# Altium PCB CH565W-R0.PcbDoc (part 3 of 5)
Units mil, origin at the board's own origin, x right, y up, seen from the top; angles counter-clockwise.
Board outline 3947.04 x 3947.04 mil, 4 copper layers (Top Layer, Layer 1, Layer 2, Bottom Layer), stack 23.756 mil thick; 204 components, 168 nets, 932 pads, 1005 vias.
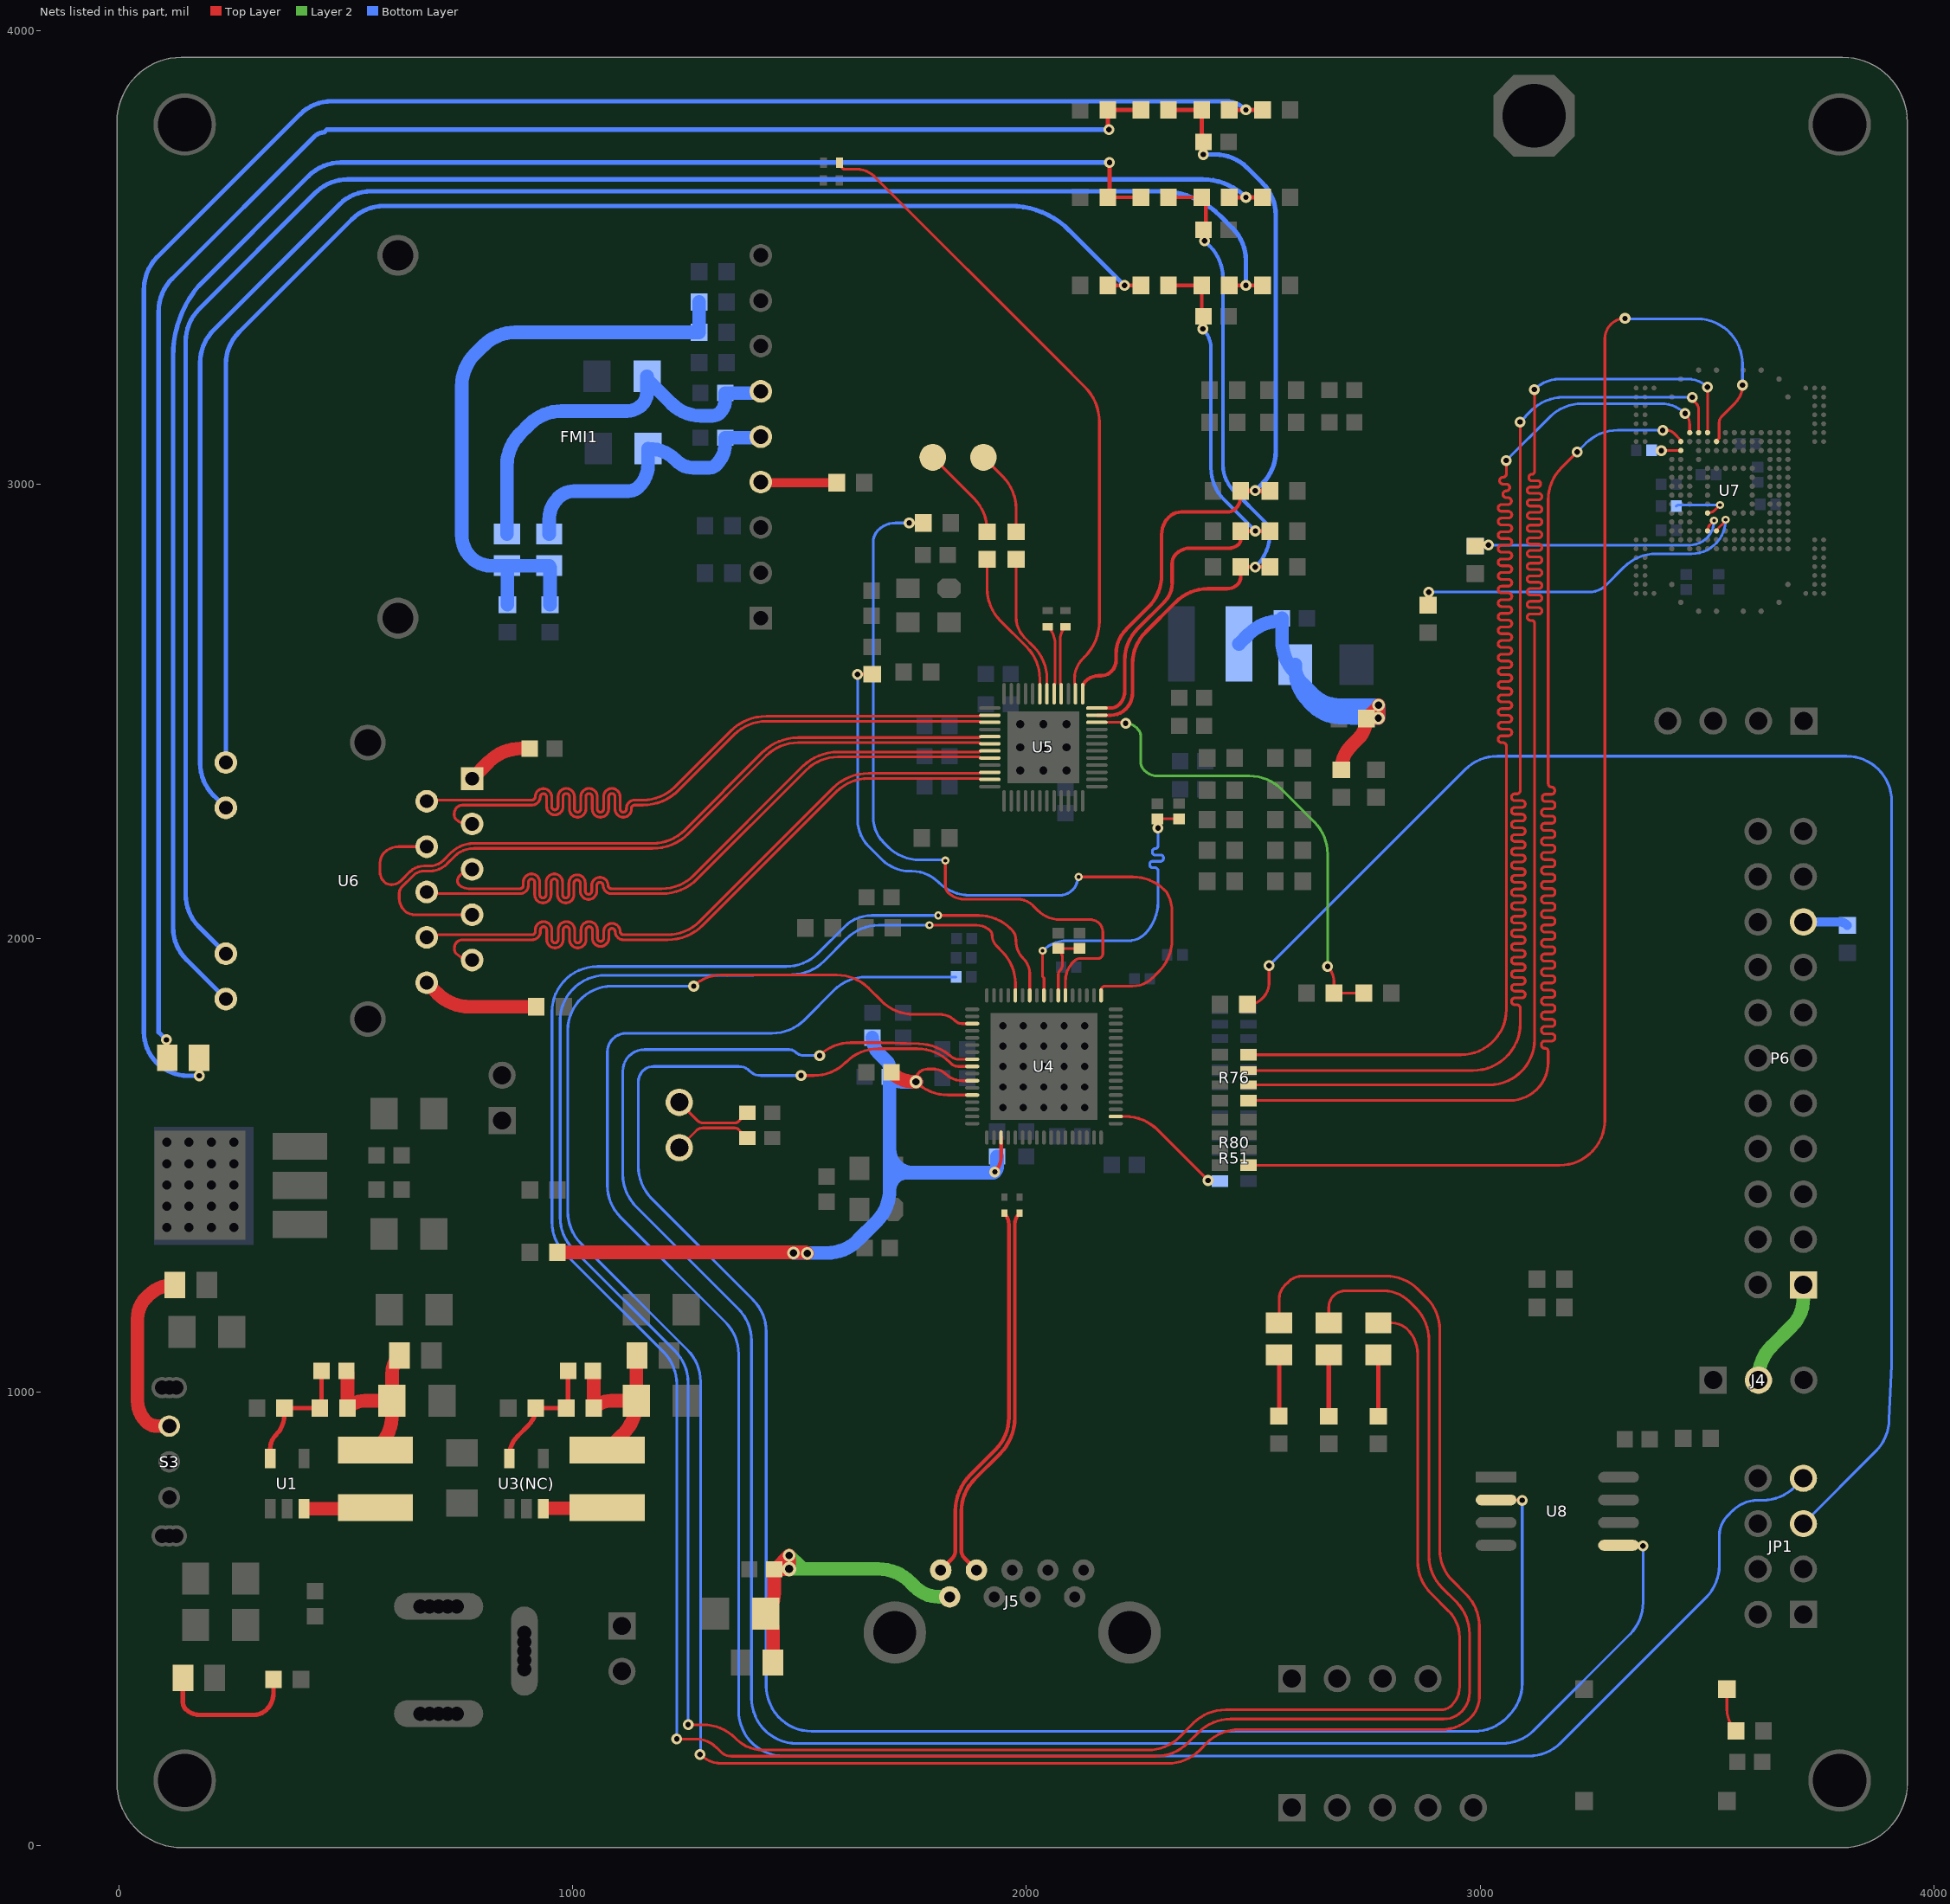
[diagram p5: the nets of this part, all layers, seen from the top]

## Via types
v1: diameter 17.72, hole 7.87, Top Layer to Bottom Layer, 556 vias
v2: diameter 24, hole 12, Top Layer to Bottom Layer, 366 vias
v3: diameter 28, hole 16, Top Layer to Bottom Layer, 63 vias
v4: diameter 17.72, hole 7.87, Top Layer to Bottom Layer, tented both sides, 8 vias
v5: diameter 24, hole 12, Top Layer to Bottom Layer, tented both sides, 5 vias
v6: diameter 26, hole 14, Top Layer to Bottom Layer, 2 vias
v7: diameter 19.68, hole 10, Top Layer to Bottom Layer, 1 vias
v8: diameter 20, hole 10, Top Layer to Bottom Layer, 1 vias
v9: diameter 28, hole 16, Top Layer to Bottom Layer, tented both sides, 1 vias
v10: diameter 32, hole 18, Top Layer to Bottom Layer, 1 vias
v11: diameter 17.72, hole 12, Top Layer to Bottom Layer, 1 vias

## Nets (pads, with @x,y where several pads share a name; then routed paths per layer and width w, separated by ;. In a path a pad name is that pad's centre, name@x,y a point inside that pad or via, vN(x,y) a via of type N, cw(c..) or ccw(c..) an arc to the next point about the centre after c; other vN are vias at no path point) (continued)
HSI_p: C30.1 U5.38 | length 1446.3
  Top Layer w6.07: C30.1@1587.84,3709.36 1590.71,3706.49 cw(c1585.97,3701.74) 1592.68,3701.74 1592.68,3701.48 ccw(c1598.75,3701.48) 1594.45,3697.19 ccw(c1598.75,3701.48) 1598.75,3695.41 1625.45,3695.41 cw(c1625.45,3639.8) 1664.77,3679.12 2071.93,3271.96 2128.33,3215.56 cw(c2049.98,3137.2) 2160.79,3137.2 2160.79,2698.77 cw(c2049.79,2698.77) 2128.28,2620.28 2124.36,2616.35 ccw(c2169.24,2571.47) 2105.76,2571.47 2105.76,2563.07 ccw(c2109.76,2563.07) 2106.93,2560.25 cw(c2104.11,2557.42) 2108.1,2557.42 U5.38@2108.1,2538.9
HSO_CK_n: R15.2 U5.43 | length 335.7
  Top Layer w6: R15.2@1913.28,2835.12 1913.28,2770.68 ccw(c2013.28,2770.68) 1942.57,2699.97 2000.07,2642.47 cw(c1929.36,2571.76) 2029.36,2571.76 U5.43@2029.36,2538.9
HSO_CK_p: R16.2 U5.42 | length 317.3
  Top Layer w6: R16.2@1977.14,2835.12 1977.14,2708.23 ccw(c2042.31,2708.23) 1996.19,2662.19 ; 1996.23,2662.15 2015.82,2642.56 cw(c1945.11,2571.85) 2045.11,2571.85 U5.42@2045.11,2538.9
HSO_n: C29.1 U5.41 | length 152.7
  Top Layer w6.07: C29.1@2047.23,2686.71 cw(c2008.67,2648.15) 2063.2,2648.15 2063.2,2563.07 cw(c2059.2,2563.07) 2062.03,2560.25 ccw(c2064.85,2557.42) 2060.86,2557.42 U5.41@2060.86,2538.9
HSO_p: C28.1 U5.40 | length 151.6
  Top Layer w6.07: U5.40@2076.61,2538.9 2076.61,2557.42 ccw(c2072.61,2557.42) 2075.44,2560.25 cw(c2078.26,2563.07) 2074.27,2563.07 2074.27,2657.81 cw(c2115.13,2657.81) C28.1@2086.23,2686.71
INTB: R35.1 R36.1 U5.34 | length 1060.9
  Top Layer w6: U5.34@2155.35,2475.91 2186.16,2475.91 ; 2187.54,2476.07 cw(c2186.16,2481.91) 2186.16,2475.91 ; v2(2218.68,2473.8) ccw(c2213.58,2468.7) 2213.58,2475.91 2186.16,2475.91 ; v2(2663.89,1937.58) cw(c2630.17,1903.86) 2677.86,1903.86 R36.1@2677.86,1879.13 R35.1@2743.57,1879.13
  Layer 2 w6: v2(2218.68,2473.8) cw(c2218.68,2440.07) 2242.53,2463.92 2245.76,2460.69 cw(c2231.12,2446.05) 2251.83,2446.05 2251.83,2389.59 ccw(c2279.93,2389.59) 2260.06,2369.72 ccw(c2289.34,2399) 2289.34,2357.59 2491.62,2357.59 cw(c2491.62,2257.59) 2562.33,2328.3 2634.6,2256.03 cw(c2563.89,2185.32) 2663.89,2185.32 v2(2663.89,1937.58)
LED0: D3.2 U4.54 | length 5823.5
  Top Layer w6: v2(1280.4,200.58) ccw(c1328.73,248.91) 1328.73,180.57 2311.21,180.57 ccw(c2311.21,280.57) 2381.92,209.85 2397.98,225.91 cw(c2468.69,155.2) 2468.69,255.2 2915.13,255.2 ccw(c2915.13,346.3) 2979.55,281.88 ccw(c2934.16,327.27) 2998.35,327.27 2998.35,482.96 ccw(c2898.35,482.96) 2969.06,553.67 2939.05,583.68 cw(c3006.69,651.31) 2911.04,651.31 2911.04,1136.81 ccw(c2811.76,1136.81) 2881.96,1207.01 2863.15,1225.82 ccw(c2792.43,1155.11) 2792.43,1255.11 2608.29,1255.11
  Top Layer w6.07: v2(1266.41,1894.11) cw(c1325.85,1834.66) 1325.85,1918.73 1347.45,1918.73 ; 1340.02,1918.46 cw(c1347.45,1818.73) 1347.45,1918.73 ; U4.54@1880.41,1811.61 1856.9,1811.61 cw(c1856.9,1829.57) 1844.2,1816.87 ccw(c1807.52,1780.18) 1807.52,1832.07 1751.28,1832.07 cw(c1751.28,1932.07) 1680.57,1861.35 1652.48,1889.44 ccw(c1581.77,1818.73) 1581.77,1918.73 1347.45,1918.73 ; D3.2@2557.01,1151.68 2557.01,1204.73 cw(c2598.61,1204.73) 2569.2,1234.14 2577.36,1242.3 cw(c2608.29,1211.37) 2608.29,1255.11
  Bottom Layer w6.07: v2(1266.41,1894.11) 1085.7,1894.11 ccw(c1085.7,1797.2) 988.79,1797.2 988.79,1397.57 ccw(c1088.79,1397.57) 1018.08,1326.86 1252.11,1092.83 cw(c1181.4,1022.12) 1281.4,1022.12 v2@1281.4,200.58
LED0/PHYAD0: C53.1 R28.2 R29.1 R58.2 R59.2 U5.35 | length 1544.5
  Top Layer w8: U5.35@2155.35,2491.66 2186.15,2491.66 ccw(c2186.15,2537.98) 2218.9,2505.23 ccw(c2183.24,2540.89) 2233.68,2540.89 2233.68,2604.28 cw(c2333.68,2604.28) 2262.97,2674.99 2328.95,2740.98 cw(c2399.66,2670.27) 2399.66,2770.27 2441.86,2770.27 ccw(c2441.86,2803.97) 2465.69,2780.14 ccw(c2450.2,2795.63) 2472.1,2795.63 R28.2@2472.1,2818.39 v2(2504.35,2818.39) R29.1@2536.59,2818.39 ; R58.2@2313.17,3633.33 R59.2@2386.48,3633.33 cw(c2364.97,3611.82) 2395.39,3611.82 C53.1@2395.39,3562.09 ; C53.1@2390.39,3562.09 2390.39,3542.61 ccw(c2398,3542.61) v2(2392.62,3537.23)
  Bottom Layer w8: v2(2392.62,3537.23) 2403.86,3525.99 cw(c2333.15,3455.28) 2433.15,3455.28 2433.15,3043.33 ccw(c2512.97,3043.33) 2456.53,2986.89 2526.81,2916.6 cw(c2503.17,2892.97) 2536.6,2892.97 2536.6,2892.07 cw(c2436.6,2892.07) 2507.31,2821.36 v2(2504.35,2818.39)
LED1: D4.2 U4.45 | length 5942.9
  Top Layer w6: v2(1229.1,234.45) 1270.53,234.45 cw(c1270.53,168.24) 1317.35,215.06 1326.5,205.9 ccw(c1349.22,228.62) 1349.22,196.49 ; v1(1805.62,2050.05) 1894.54,2050.05 cw(c1894.54,1950.05) 1965.25,2020.76 1966.93,2019.08 cw(c1943.64,1995.78) 1976.58,1995.78 ccw(c2035.26,1995.78) 1986.42,1963.26 ccw(c2035.26,1995.78) 1993.77,1954.29 cw(c1961.59,1922.11) 2007.1,1922.11 U4.45@2007.1,1873.9 ; D4.2@2666.38,1151.68 2666.38,1185.84 cw(c2702.74,1185.84) 2677.03,1211.54 cw(c2703.47,1185.11) 2703.47,1222.49 2722.55,1222.49
  Top Layer w6.07: 1349.22,196.49 2285.24,196.49 ccw(c2285.24,296.49) 2355.95,225.78 2379.26,249.09 cw(c2449.97,178.38) 2449.97,278.38 2919.97,278.38 ccw(c2919.97,333.47) 2958.92,294.52 ccw(c2915.95,337.49) 2976.73,337.49 2976.73,466.1 ccw(c2876.73,466.1) 2947.44,536.81 2916.43,567.82 cw(c2987.14,638.53) 2887.14,638.53 2887.14,1114.26 ccw(c2787.14,1114.26) 2857.85,1184.97 2843.63,1199.19 ccw(c2787.36,1142.92) 2787.36,1222.49 2722.55,1222.49
  Bottom Layer w6: v2(1229.1,234.45) 1229.1,1016.88 ccw(c1129.1,1016.88) 1199.81,1087.59 983.16,1304.24 cw(c1053.87,1374.95) 953.87,1374.95 953.87,1837.59 cw(c1053.87,1837.59) 1053.73,1937.59 cw(c1053.87,1837.59) 1053.87,1937.59 1470.08,1937.59 ccw(c1470.08,2037.59) 1540.79,1966.88 1599.42,2025.5 cw(c1658.68,1966.23) 1658.68,2050.05 v1(1805.62,2050.05)
LED1/CFG_LDO0: C58.1 R37.2 R38.1 R71.2 R72.2 U5.36 | length 1320.4
  Top Layer w8: U5.36@2155.35,2507.41 2185.36,2507.41 ccw(c2185.36,2534.62) 2204.61,2515.38 ccw(c2175.97,2544.02) 2216.47,2544.02 2216.47,2612.35 cw(c2316.47,2612.35) 2245.76,2683.06 2304.03,2741.33 ccw(c2262.41,2782.95) 2321.27,2782.95 2321.27,2826.36 cw(c2350.68,2826.36) 2329.88,2847.16 cw(c2360.56,2816.49) 2360.56,2859.87 2446.75,2859.87 ccw(c2446.75,2890.29) 2468.26,2868.78 ccw(c2458.98,2878.06) 2472.1,2878.06 R37.2@2472.1,2897.13 R38.1@2536.59,2897.13 ; R71.2@2313.17,3439.1 R72.2@2386.48,3439.1 2386.48,3380.36 ccw(c2399.84,3380.36) C58.1@2390.39,3370.91 ccw(c2394.06,3367.25) 2388.87,3367.25 v2(2388.87,3343.33)
  Bottom Layer w8: v2(2388.87,3343.33) cw(c2345.72,3300.18) 2406.75,3300.18 2406.75,3037.06 ccw(c2506.75,3037.06) 2436.04,2966.35 v2(2504.64,2897.75)
LED2: D5.2 U4.47 | length 5531.7
  Top Layer w6: v2(1254.15,266) 1287.31,266 cw(c1287.31,166) 1358.02,236.71 1360.58,234.15 ccw(c1418.62,292.2) 1418.62,210.11 2268.45,210.11 ccw(c2268.45,307.09) 2337.03,238.52 2368.08,269.57 cw(c2438.79,198.86) 2438.79,298.86 2914.27,298.86 ccw(c2914.27,331.39) 2937.27,308.38 ccw(c2895.1,350.55) 2954.74,350.55 2954.74,458.9 ccw(c2873.41,458.9) 2930.92,516.4 2891.67,555.65 cw(c2962.38,626.36) 2862.38,626.36 2862.38,1082.73 ccw(c2784.65,1082.73) 2839.61,1137.7 ccw(c2805.86,1103.95) 2805.86,1151.68 D5.2@2775.75,1151.68 ; v1(1786.1,2028.55) 1890.11,2028.55 cw(c1890.11,1985.28) 1920.71,2015.87 cw(c1912.39,2007.55) 1924.15,2007.55 ccw(c1959.87,2007.55) 1934.61,1982.3 1946.31,1970.6 cw(c1875.6,1899.89) 1975.6,1899.89 U4.47@1975.6,1873.9
  Bottom Layer w6: v2(1254.15,266) 1254.15,1019.48 ccw(c1154.15,1019.48) 1224.86,1090.19 1001.28,1313.77 cw(c1071.99,1384.48) 971.99,1384.48 971.99,1818.23 cw(c1071.99,1818.23) 972.05,1821.42 cw(c1071.99,1818.23) 1071.99,1918.23 1398.39,1918.23 1483.26,1920.24 cw(c1483.42,1914.24) 1483.42,1920.24 ccw(c1483.42,2020.24) 1554.13,1949.53 1604,1999.39 cw(c1674.38,1929) 1674.38,2028.55 v1(1786.1,2028.55)
LED2/CFG_LDO1: C54.1 R39.2 R40.1 R67.2 R68.2 U5.37 | length 1758.8
  Top Layer w8: U5.37@2123.85,2538.9 2123.85,2551.15 cw(c2145.58,2551.15) 2130.21,2566.51 2130.33,2566.63 cw(c2159.06,2537.9) 2159.06,2578.53 2164.09,2578.53 ccw(c2164.09,2611.36) 2187.31,2588.15 ccw(c2162.64,2612.81) 2197.53,2612.81 2197.53,2627.01 cw(c2273.45,2627.01) 2219.76,2680.7 2268.71,2729.65 ccw(c2198,2800.36) 2298,2800.36 2298,2889.84 cw(c2352.17,2889.84) 2313.87,2928.15 cw(c2341.34,2900.68) 2341.34,2939.53 2442.41,2939.53 ccw(c2442.41,2966.39) 2461.41,2947.39 ccw(c2435.58,2973.22) 2472.1,2973.22 R39.2@2472.1,2985.87
  Top Layer w10: R67.2@2313.17,3826.22 R68.2@2386.48,3826.22 2386.48,3776.61 ccw(c2416.91,3776.61) C54.1@2395.39,3755.1 ; v2(2389.9,3727.84) ccw(c2388.72,3729.02) 2390.39,3729.02 C54.1@2390.39,3755.1 ; R39.2@2472.1,2985.87 R40.1@2536.59,2985.87
  Bottom Layer w10: v2(2389.9,3727.84) 2415.82,3727.84 cw(c2415.82,3627.84) 2486.53,3698.55 2520.34,3664.74 cw(c2449.63,3594.03) 2549.63,3594.03 2549.63,3073.45 cw(c2449.63,3073.45) 2520.34,3002.74 v2(2504.19,2986.59) ccw(c2514.19,2986.59) v2@2504.19,2986.51
LED_blue_n: D2.2 R68.1 R69.1 | length 4549.1
  Top Layer w10: D2.2@175.98,1736.01 175.98,1697.89 ccw(c177.69,1697.89) v2(176.48,1696.68) ; R68.1@2447.11,3826.22 v2(2483.77,3826.22) R69.1@2520.42,3826.22
  Bottom Layer w10: v2(176.48,1696.68) 151.66,1696.68 cw(c151.66,1794.39) 82.57,1725.3 cw(c150.27,1793) 54.53,1793 54.53,3300.97 54.53,3430.89 cw(c154.53,3430.89) 55.44,3444.37 cw(c154.53,3430.89) 83.82,3501.61 398.2,3815.99 cw(c468.92,3745.28) 468.92,3845.28 2437.74,3845.28 cw(c2437.74,3780.19) v2(2483.77,3826.22)
LED_blue_p: D2.1 R66.2 R67.1 | length 4051.4
  Top Layer w10: v2(103.69,1775.98) cw(c103.69,1773.77) 105.9,1773.77 D2.1@105.9,1736.01 ; v2(2181.54,3782.57) cw(c2187.14,3788.17) 2179.23,3788.17 R66.2@2179.23,3826.22 R67.1@2252.54,3826.22
  Bottom Layer w10: v2(103.69,1775.98) 87,1792.65 87,3242.91 87,3382.79 cw(c187,3382.79) 87.44,3392.17 cw(c187,3382.79) 116.29,3453.5 430.48,3767.69 cw(c451.38,3746.8) 451.38,3776.35 457.6,3782.57 v2(2181.54,3782.57)
LED_green_n: R72.1 R73.1 U6.12 | length 3681.8
  Top Layer w8: R72.1@2447.11,3439.1 v2(2483.77,3439.1) R73.1@2520.42,3439.1
  Bottom Layer w10: U6.12@234.95,2287.54 207.86,2314.63 cw(c278.57,2385.34) 178.57,2385.34 178.57,3269.55 cw(c278.57,3269.55) 180.33,3288.23 cw(c278.57,3269.55) 207.86,3340.26 485.02,3617.42 cw(c555.73,3546.71) 555.73,3646.71 2295.99,3646.71 cw(c2295.99,3461.18) 2427.18,3592.37 2454.48,3565.07 cw(c2383.77,3494.36) 2483.77,3494.36 v2(2483.77,3439.1)
LED_green_p: R70.2 R71.1 U6.11 | length 3157
  Top Layer w8: R70.2@2179.23,3439.1 v2(2215.88,3439.1) R71.1@2252.54,3439.1
  Bottom Layer w10: U6.11@234.95,2387.54 234.95,3265.49 cw(c334.95,3265.49) 264.24,3336.2 513.1,3585.06 cw(c583.81,3514.35) 583.81,3614.35 1964.21,3614.35 cw(c1964.21,3429.85) 2094.67,3560.31 v2(2215.88,3439.1)
LED_yellow_n: R59.1 R61.1 U6.13 | length 3966.9
  Top Layer w10: R59.1@2447.11,3633.33 v2(2483.77,3633.33) R61.1@2520.42,3633.33
  Bottom Layer w10: U6.13@234.95,1965.89 175.89,2024.94 cw(c246.6,2095.65) 146.6,2095.65 146.6,3315.92 cw(c246.6,3315.92) 175.89,3386.63 432.82,3643.57 cw(c503.53,3572.85) 442.14,3651.79 cw(c503.53,3572.85) 457.66,3661.71 cw(c503.53,3572.85) 503.53,3672.85 2388.35,3672.85 cw(c2388.35,3537.92) v2(2483.77,3633.33)
LED_yellow_p: R57.2 R58.1 U6.14 | length 3897.1
  Top Layer w8: R57.2@2179.23,3633.33 R58.1@2252.54,3633.33
  Top Layer w10: R57.2@2179.23,3633.33 ccw(c2174.48,3638.08) 2181.2,3638.08 2183.11,3640 v2(2183.11,3709.99)
  Bottom Layer w10: U6.14@234.95,1865.88 147.83,1953.01 cw(c218.54,2023.72) 118.54,2023.72 118.54,3282.88 cw(c360.1,3282.84) 173.97,3436.81 417.86,3680.7 cw(c488.57,3609.99) 488.57,3709.99 v2(2183.11,3709.99)
MAC_125M: R62.2 U4.40 | length 1595
  Top Layer w6: v2(1741.47,2915.5) 1741.53,2915.44 R62.2@1772.45,2915.44 ; v1(1821.29,2171.08) 1821.29,2114.81 ccw(c1841.25,2114.81) 1827.13,2100.69 ccw(c1862.6,2136.16) 1862.6,2086 1979.94,2086 cw(c1979.94,2037.54) 2014.21,2071.81 2024.38,2061.64 ccw(c2074.66,2111.92) 2042.88,2048.31 ccw(c2074.66,2111.92) 2074.66,2040.82 2140.85,2040.82 cw(c2140.85,2013.19) 2168.47,2013.19 2168.47,1966.22 cw(c2157.43,1966.22) 2157.43,1955.18 2118.97,1955.18 ccw(c2118.97,1934.69) 2104.48,1949.18 ccw(c2149.48,1904.17) 2091.15,1929.62 ccw(c2149.48,1904.17) 2085.84,1904.17 U4.40@2085.84,1873.9
  Bottom Layer w6: v2(1741.47,2915.5) 1711.59,2915.5 ccw(c1711.59,2860.6) 1672.77,2899.42 ccw(c1698.64,2873.55) 1662.05,2873.55 1662.05,2267.4 ccw(c1742.76,2267.4) 1685.69,2210.32 1694.28,2201.73 ccw(c1764.99,2272.44) 1764.99,2172.44 v1@1821.29,2172.44
MAC_EMCO: R60.2 U4.35 | length 1479.9
  Top Layer w6: v2(1627.69,2581.47) cw(c1629.99,2579.17) 1629.99,2582.42 R60.2@1659.93,2582.42 ; v1(2115,2135) 2234.16,2135 2234.26,2135.1 cw(c2234.26,2035.1) 2304.97,2105.81 2309.07,2101.71 cw(c2234.2,2058.14) 2320.82,2058.14 2320.82,1996.81 cw(c2220.82,1996.81) 2291.53,1926.1 2277.83,1912.39 cw(c2234.11,1956.1) 2234.11,1894.28 2173.47,1894.28 ccw(c2173.47,1885.39) 2164.58,1885.39 U4.35@2164.58,1873.9
  Bottom Layer w6: v2(1627.69,2581.47) 1627.69,2261.65 ccw(c1711.68,2261.65) 1652.29,2202.27 1681.45,2173.11 ccw(c1742.73,2234.39) 1742.73,2147.72 1747.55,2147.72 cw(c1747.55,2065.38) 1805.77,2123.61 ccw(c1876.18,2194.01) 1876.18,2094.44 2072.89,2094.44 ccw(c2072.89,2135.4) 2101.85,2106.44 ccw(c2074.94,2133.35) 2113,2133.35 2114.65,2135 v1(2115,2135)
MCU_3V3: C34.1 C35.2 C37.2 C46.2 R85.2 U4.3 U4.62 U4.64 | length 2087.9
  Top Layer w6.07: U4.64@1880.41,1654.13 1826.85,1654.13 cw(c1826.85,1753.51) v3(1756.58,1683.24) 1756.58,1688.57 cw(c1777.53,1688.57) 1762.71,1703.38 cw(c1782.17,1683.92) 1782.17,1711.44 1796.82,1711.44 cw(c1796.82,1677.35) 1800.23,1711.27 cw(c1796.82,1677.35) 1820.92,1701.46 ccw(c1859.15,1739.69) 1859.15,1685.63 U4.62@1880.41,1685.63
  Top Layer w8: v5(1930.24,1484.81) ccw(c1896.78,1518.27) 1944.11,1518.27 U4.3@1944.11,1560.34
  Top Layer w30: R85.2@965.93,1307.5 v3@1482.53,1307.5 ; v3(1486.31,1305.93) ccw(c1482.53,1302.15) v3@1482.53,1307.5 ; v3(1517,1305.31) ccw(c1511.72,1300.04) 1511.72,1307.5 v3@1482.53,1307.5 ; C37.2@1702.17,1704.14 ccw(c1752.63,1754.6) 1752.63,1683.24 v3(1756.58,1683.24)
  Bottom Layer w30: v3(1486.31,1305.93) 1559.86,1305.93 ccw(c1559.86,1403.24) 1628.67,1334.43 1669.06,1374.83 ccw(c1598.35,1445.54) 1698.35,1445.54 ; C35.2@1660.22,1780.43 ccw(c1708.7,1780.43) 1674.42,1746.15 1691.76,1728.8 cw(c1675.87,1712.9) 1698.35,1712.9 C34.1@1698.35,1694.32 ; 1698.35,1545.55 1698.35,1534.22 ; v3(1756.58,1683.24) 1725.09,1683.24 cw(c1725.09,1721.06) C34.1@1698.35,1694.32 ; C46.2@1935.23,1518.66 1935.23,1496.85 cw(c1918.2,1496.85) v5(1930.24,1484.81) cw(c1925.78,1489.28) 1925.78,1482.96 1749.61,1482.96 ; 1698.35,1445.54 cw(c1735.77,1445.54) 1735.77,1482.96 ; 1698.35,1445.54 1698.35,1482.96 ; 1698.35,1482.96 1698.35,1534.22 ; 1698.35,1482.96 1735.77,1482.96 ; 1698.35,1534.22 ccw(c1749.61,1534.22) 1749.61,1482.96 ; 1698.35,1534.22 C34.1@1698.35,1694.32 ; 1735.77,1482.96 1749.61,1482.96
MDI0_n: U5.3 U6.3 | length 1621.3
  Top Layer w6.07: U6.3@777.86,2251.78 767.69,2251.78 cw(c767.69,2287.75) 742.26,2262.32 cw(c751.53,2271.58) 738.43,2271.58 738.43,2274.19 cw(c758.08,2274.19) 744.18,2288.08 744.46,2288.36 cw(c756.66,2276.17) 756.66,2293.41 881.43,2293.41 909.98,2293.41 ccw(c909.98,2311.52) 928.08,2311.52 cw(c935.12,2311.52) 942.15,2311.52 942.15,2290.06 ccw(c960.25,2290.06) 978.36,2290.06 978.36,2311.98 cw(c985.39,2311.98) 992.43,2311.98 992.43,2284.79 ccw(c1010.53,2284.79) 1028.63,2284.79 1028.63,2311.98 cw(c1035.66,2311.98) 1042.7,2311.98 1042.7,2284.79 ccw(c1060.8,2284.79) 1078.9,2284.79 1078.9,2311.98 cw(c1085.94,2311.98) 1092.97,2311.98 1092.97,2284.79 ccw(c1111.08,2284.79) 1129.18,2284.79 1129.18,2286.38 cw(c1136.21,2286.38) 1136.21,2293.41 1144.78,2293.41 1154.38,2293.41 ccw(c1154.38,2404.3) 1232.79,2325.89 1355.86,2448.96 cw(c1426.57,2378.25) 1426.57,2478.25 1894.96,2478.25 cw(c1894.96,2474.26) 1897.78,2477.08 ccw(c1900.61,2479.91) 1900.61,2475.91 U5.3@1919.13,2475.91
MDI0_p: U5.2 U6.2 | length 1620.2
  Top Layer w6.07: U6.2@677.86,2301.78 cw(c684.38,2295.26) 684.38,2304.48 881.43,2304.48 909.98,2304.48 ccw(c909.98,2311.52) 917.01,2311.52 cw(c935.12,2311.52) 953.22,2311.52 953.22,2290.06 ccw(c960.25,2290.06) 967.29,2290.06 967.29,2311.98 cw(c985.39,2311.98) 1003.49,2311.98 1003.49,2284.79 ccw(c1010.53,2284.79) 1017.56,2284.79 1017.56,2311.98 cw(c1035.66,2311.98) 1053.77,2311.98 1053.77,2284.79 ccw(c1060.8,2284.79) 1067.84,2284.79 1067.84,2311.98 cw(c1085.94,2311.98) 1104.04,2311.98 1104.04,2284.79 ccw(c1111.08,2284.79) 1118.11,2284.79 1118.11,2286.38 cw(c1136.21,2286.38) 1136.21,2304.48 1144.78,2304.48 1154.31,2304.48 ccw(c1154.31,2404.48) 1225.02,2333.77 1296.38,2405.14 1348.06,2456.82 cw(c1426.52,2378.36) 1426.52,2489.32 1894.96,2489.32 ccw(c1894.96,2493.31) 1897.78,2490.49 cw(c1900.61,2487.66) 1900.61,2491.66 U5.2@1919.13,2491.66
MDI1_n: U5.6 U6.7 | length 1621.4
  Top Layer w6.07: U6.7@777.86,2051.78 651.16,2051.78 cw(c651.16,2084.04) 628.34,2061.23 cw(c654.82,2087.71) 617.38,2087.71 617.38,2099.56 cw(c636.41,2099.56) 622.95,2113.02 648.16,2138.22 cw(c671.81,2114.56) 671.81,2148.02 684.6,2148.02 ccw(c684.6,2201.55) 722.45,2163.7 739.03,2180.27 cw(c781.56,2137.74) 781.56,2197.89 1175.92,2197.89 ccw(c1175.92,2308.85) 1254.39,2230.39 1425.71,2401.72 cw(c1496.42,2331.01) 1496.42,2431.01 1894.96,2431.01 cw(c1894.96,2427.01) 1897.78,2429.84 ccw(c1900.61,2432.66) 1900.61,2428.67 U5.6@1919.13,2428.67
MDI1_p: U5.5 U6.4 | length 1620.9
  Top Layer w6.07: U6.4@677.86,2201.78 616.15,2201.78 ccw(c616.15,2156.64) 584.23,2188.56 ccw(c606.41,2166.38) 575.04,2166.38 575.04,2145.12 ccw(c603.81,2145.12) 583.46,2124.77 ccw(c599.89,2141.2) 599.89,2117.97 ccw(c599.89,2147.8) 620.98,2126.7 640.33,2146.05 cw(c671.81,2114.56) 671.81,2159.09 684.52,2159.09 ccw(c684.52,2201.76) 714.69,2171.58 731.23,2188.13 cw(c781.52,2137.84) 781.52,2208.96 1175.88,2208.96 ccw(c1175.88,2308.96) 1246.59,2238.25 1417.92,2409.57 cw(c1496.38,2331.11) 1496.38,2442.07 1894.96,2442.07 ccw(c1894.96,2446.07) 1897.78,2443.24 cw(c1900.61,2440.42) 1900.61,2444.41 U5.5@1919.13,2444.41
MDI2_n: U5.8 U6.6 | length 1620.6
  Top Layer w6.07: U6.6@677.86,2101.78 ccw(c686.89,2110.81) 686.89,2098.04 875.16,2098.04 883.73,2098.04 ccw(c883.73,2116.15) 901.83,2116.15 901.83,2123.52 cw(c908.86,2123.52) 915.9,2123.52 915.9,2095.76 ccw(c934,2095.76) 952.1,2095.76 952.1,2123.52 cw(c959.14,2123.52) 966.17,2123.52 966.17,2095.76 ccw(c984.28,2095.76) 1002.38,2095.76 1002.38,2121.59 cw(c1009.41,2121.59) 1016.45,2121.59 1016.45,2103.58 ccw(c1034.55,2103.58) 1052.65,2103.58 1052.65,2116.15 cw(c1059.69,2116.15) 1066.72,2116.15 ccw(c1084.82,2116.15) 1084.82,2098.04 1179.3,2098.04 1196.21,2098.04 ccw(c1196.21,2207.58) 1273.66,2130.13 1513.76,2370.22 cw(c1584.47,2299.51) 1584.47,2399.51 1894.96,2399.51 cw(c1894.96,2395.52) 1897.78,2398.34 ccw(c1900.61,2401.16) 1900.61,2397.17 U5.8@1919.13,2397.17
MDI2_p: U5.7 U6.5 | length 1620.1
  Top Layer w6.07: 749.65,2136.89 ccw(c759.18,2127.38) 745.72,2127.38 745.72,2125.35 ccw(c755.81,2125.35) 748.67,2118.22 ccw(c770.65,2140.19) 770.65,2109.11 875.16,2109.11 883.73,2109.11 ccw(c883.73,2116.15) 890.76,2116.15 890.76,2123.52 cw(c908.86,2123.52) 926.97,2123.52 926.97,2095.76 ccw(c934,2095.76) 941.04,2095.76 941.04,2123.52 cw(c959.14,2123.52) 977.24,2123.52 977.24,2095.76 ccw(c984.28,2095.76) 991.31,2095.76 991.31,2121.59 cw(c1009.41,2121.59) 1027.51,2121.59 1027.51,2103.58 ccw(c1034.55,2103.58) 1041.58,2103.58 1041.58,2116.15 cw(c1059.69,2116.15) 1077.79,2116.15 ccw(c1084.82,2116.15) 1084.82,2109.11 1179.3,2109.11 1196.03,2109.11 ccw(c1196.03,2208) 1265.96,2138.08 1505.96,2378.08 cw(c1584.42,2299.62) 1584.42,2410.58 1894.96,2410.58 ccw(c1894.96,2414.57) 1897.78,2411.75 cw(c1900.61,2408.92) 1900.61,2412.92 U5.7@1919.13,2412.92 ; 749.66,2136.89 755.14,2142.37 cw(c777.86,2119.64) U6.5@777.86,2151.78 ccw(c777.86,2132.27) U6.5@764.06,2146.07
MDI3_n: U5.11 U6.9 | length 1694.7
  Top Layer w6.07: U6.9@777.86,1951.78 cw(c777.86,2001.84) 742.47,1966.44 cw(c750.52,1974.5) 739.13,1974.5 739.13,1979.19 cw(c756.46,1979.19) 744.21,1991.45 cw(c756.18,1979.47) 756.18,1996.41 860.94,1996.41 861.01,1996.47 ; 891,1996.47 861.01,1996.47 ; 1155.46,1996.47 1111.37,1996.47 ; U5.11@1919.13,2349.93 1900.61,2349.93 cw(c1900.61,2353.92) 1897.78,2351.1 ccw(c1894.96,2348.27) 1894.96,2352.27 1651.77,2352.27 ccw(c1651.77,2252.27) 1581.05,2322.98 1286.96,2028.88 cw(c1208.72,2107.12) 1208.72,1996.47 1176.69,1996.47 1111.37,1996.47 ; 861.01,1996.47 901.71,1996.47 910.28,1996.47 ccw(c910.28,2014.58) 928.38,2014.58 928.38,2018.44 cw(c935.42,2018.44) 942.45,2018.44 942.45,1996.64 ccw(c960.55,1996.64) 978.66,1996.64 978.66,2018.44 cw(c985.69,2018.44) 992.72,2018.44 992.72,1996.64 ccw(c1010.83,1996.64) 1028.93,1996.64 1028.93,2018.44 cw(c1035.96,2018.44) 1043,2018.44 1043,2000.01 ccw(c1061.1,2000.01) 1079.2,2000.01 1079.2,2014.58 cw(c1086.24,2014.58) 1093.27,2014.58 ccw(c1111.37,2014.58) 1111.37,1996.47
MDI3_p: U5.10 U6.8 | length 1664.7
  Top Layer w6.07: U6.8@677.86,2001.78 cw(c691.92,1987.72) 691.92,2007.61 859.75,2007.61 859.81,2007.54 891,2007.54 901.71,2007.54 910.28,2007.54 ccw(c910.28,2014.58) 917.31,2014.58 917.31,2018.44 cw(c935.42,2018.44) 953.52,2018.44 953.52,1996.64 ccw(c960.55,1996.64) 967.59,1996.64 967.59,2018.44 cw(c985.69,2018.44) 1003.79,2018.44 1003.79,1996.64 ccw(c1010.83,1996.64) 1017.86,1996.64 1017.86,2018.44 cw(c1035.96,2018.44) 1054.07,2018.44 1054.07,2000.01 ccw(c1061.1,2000.01) 1068.14,2000.01 1068.14,2014.58 cw(c1086.24,2014.58) 1104.34,2014.58 ccw(c1111.37,2014.58) 1111.37,2007.54 ; 1155.46,2007.54 1111.37,2007.54 ; U5.10@1919.13,2365.67 1900.61,2365.67 ccw(c1900.61,2361.68) 1897.78,2364.5 cw(c1894.96,2367.33) 1894.96,2363.33 1761.62,2363.33 1651.62,2363.33 ccw(c1651.62,2252.63) 1573.33,2330.91 1279.26,2036.83 cw(c1208.54,2107.54) 1208.54,2007.54 1176.69,2007.54 1111.37,2007.54
MISO: JP1.5 R34.2 | length 3405
  Top Layer w6: R34.2@2487.06,1847.87 R34.2@2493.5,1854.3 ; R34.2@2487.06,1853.87 ccw(c2487.06,1901.6) R34.2@2493.5,1854.3 ; v2(2534.8,1939.56) 2534.8,1901.6 cw(c2487.06,1901.6) 2534.49,1896.19 cw(c2487.06,1901.6) R34.2@2493.5,1854.3
  Bottom Layer w6: v2(2534.8,1939.56) 2967.16,2371.92 cw(c3037.87,2301.21) 3037.87,2401.21 3808.13,2401.21 cw(c3808.13,2302.32) 3878.06,2372.25 cw(c3807.35,2301.53) 3907.35,2301.53 3907.35,1063.69 cw(c3796.35,1063.69) 3907.22,1058.42 3901.73,939.99 ccw(c3907.73,939.71) 3901.73,939.71 cw(c3801.73,939.71) 3872.44,869 JP1.5@3712.66,709.23
MISO1: U4.60 U8.2 | length 4472.2
  Top Layer w6.07: v2(1502.96,1697.04) 1531.07,1697.04 ccw(c1531.07,1797.04) 1601.78,1726.33 1602.64,1727.19 cw(c1672.6,1657.23) 1672.6,1756.17 1759.79,1756.17 cw(c1759.79,1656.17) 1830.5,1726.88 1833.54,1723.85 ccw(c1849.77,1740.08) 1849.77,1717.12 U4.60@1880.41,1717.12 ; U8.2@3035.36,761.58 3090.59,761.58 cw(c3090.59,758.38) v2(3092.85,760.64)
  Bottom Layer w6.07: v2(1502.96,1697.04) 1414.32,1697.04 cw(c1414.32,1731.19) 1390.18,1707.04 ccw(c1365.43,1682.29) 1365.43,1717.3 1178.02,1717.3 ccw(c1178.02,1683.67) 1144.39,1683.67 1144.39,1496.98 ccw(c1244.39,1496.98) 1173.68,1426.27 1397.05,1202.91 cw(c1326.34,1132.19) 1426.34,1132.19 1426.34,424.01 1426.34,351.49 ccw(c1526.34,351.49) 1526.34,251.49 2987.41,251.49 ccw(c2987.41,351.49) 3058.12,280.78 3063.56,286.22 ccw(c2992.85,356.93) 3092.85,356.93 v2(3092.85,760.64)
MOSI: JP1.7 R20.2 | length 5115
  Bottom Layer w6: R20.2@1844.8,1914.38 1646.21,1914.38 ccw(c1646.21,1814.38) 1575.5,1885.09 1510.02,1819.61 cw(c1439.31,1890.32) 1439.31,1790.32 1117.38,1790.32 ccw(c1117.38,1749.06) 1076.11,1749.06 1076.11,1455.17 ccw(c1176.11,1455.17) 1105.4,1384.45 1336.04,1153.81 cw(c1265.33,1083.1) 1365.33,1083.1 1365.33,296.91 ccw(c1465.33,296.91) 1465.33,196.91 1531.43,196.91 3107.02,196.91 ccw(c3107.02,296.91) 3177.73,226.2 3498.08,546.55 ccw(c3427.37,617.26) 3527.37,617.26 3527.37,681.95 cw(c3591.26,681.95) 3546.08,727.12 3556.74,737.78 ; 3556.77,737.81 cw(c3612.26,682.26) 3587.5,756.77 cw(c3612.26,682.26) 3612.26,760.77 3622.79,760.77 ccw(c3622.79,860.77) 3693.5,790.06 JP1.7@3712.66,809.23
MOSI1: U4.59 U8.5 | length 4654.2
  Top Layer w6.07: v2(1543.99,1741.25) cw(c1612.26,1672.98) 1612.26,1769.54 1680.69,1769.54 1762.89,1767.2 cw(c1759.79,1656.17) 1827.45,1744.26 1831.26,1741.33 cw(c1827.58,1736.51) 1831.84,1740.83 1831.87,1740.8 ccw(c1851.06,1760.04) 1851.06,1732.87 U4.59@1880.41,1732.87 ; U8.5@3305.36,661.58 ccw(c3308.24,664.46) 3308.24,660.38 v2(3359.33,660.38)
  Bottom Layer w6.07: v2(1543.99,1741.25) 1508.99,1741.25 cw(c1508.99,1766.64) 1491.04,1748.69 ccw(c1477.42,1735.07) 1477.42,1754.33 1157.72,1754.33 ccw(c1157.72,1706.63) 1110.03,1706.63 1110.03,1479.31 ccw(c1210.03,1479.31) 1139.32,1408.6 1364.49,1183.42 cw(c1293.78,1112.71) 1393.78,1112.71 1393.78,324.57 ccw(c1493.78,324.57) 1493.78,224.57 2930.39,224.57 3048.2,224.57 ccw(c3048.2,324.57) 3118.91,253.86 3330.04,464.98 ccw(c3259.33,535.69) 3359.33,535.69 v2(3359.33,660.38)
NetC1_2: C1.2 C4.2 L1.2 R1.1 R89.1 | length 408.6
  Top Layer w30: C4.2@500.73,1045.86 cw(c495.11,1040.24) 503.06,1040.24 R1.1@503.06,964.09 cw(c541.59,925.56) 541.59,980.05 C1.2@601.33,980.05 ; L1.2@564.59,871.4 572.04,878.85 ccw(c501.33,949.57) 601.33,949.57 C1.2@601.33,980.05 ; R89.1@617.88,1079.72 ccw(c657.83,1039.77) 601.33,1039.77 C1.2@601.33,980.05
NetC4_1: C4.1 R1.2 R3.2 U1.5 | length 280.7
  Top Layer w10: U1.5@332.87,852.63 332.87,874.69 cw(c374.77,874.69) 345.14,904.32 ccw(c299.07,950.39) 364.23,950.39 R3.2@364.23,964.09 R1.2@442.43,964.09 ccw(c434.46,972.06) 445.73,972.06 C4.1@445.73,1045.86
NetC12_1: C12.1 R4.2 R5.2 U3(NC).5 | length 280.7
  Top Layer w10: 860,852.63 860,857.86 cw(c923.26,857.86) 878.53,902.59 903.05,927.12 ccw(c866.08,964.09) R5.2@918.37,964.09 R4.2@985.52,964.09 ccw(c976.01,973.61) 989.47,973.61 C12.1@989.47,1045.86
NetC12_2: C12.2 C13.2 L3.2 R4.1 R90.1 | length 411.5
  Top Layer w30: C12.2@1044.47,1045.86 cw(c1040.39,1041.79) 1046.15,1041.79 R4.1@1046.15,964.09 cw(c1084.69,925.56) 1084.69,980.05 C13.2@1139.85,980.05 ; L3.2@1075.44,871.49 L3.2@1075.53,871.4 1110.56,906.43 ccw(c1039.85,977.14) 1139.85,977.14 C13.2@1139.85,980.05 ; R90.1@1141.72,1079.72 ccw(c1146.24,1075.2) 1139.85,1075.2 C13.2@1139.85,980.05
NetC19_1: C19.1 C20.1 FMI1.6 L5.2 | length 900.9
  Bottom Layer w30: L5.2@854.63,2891.15 854.63,3041.59 cw(c954.63,3041.59) 881.55,3109.85 cw(c954.63,3041.59) 883.92,3112.31 904.4,3132.79 cw(c975.11,3062.08) 975.11,3162.08 1118.85,3162.08 ccw(c1118.85,3209.11) 1152.1,3175.85 ccw(c1124.5,3203.45) 1160.76,3189 ccw(c1124.5,3203.45) 1163.53,3203.45 C19.1@1163.53,3232.55 ; C19.1@1163.53,3238.71 C19.1@1163.53,3232.55 ; FMI1.6@1414.36,3205.51 cw(c1405.46,3214.41) 1405.46,3201.83 C20.1@1336.16,3201.83 1336.16,3186.9 cw(c1296.49,3186.9) 1324.54,3158.84 cw(c1307.11,3176.27) 1307.11,3151.62 1282.05,3151.62 cw(c1282.05,3242.38) 1217.88,3178.21 C19.1@1163.53,3232.55
NetC21_1: C21.1 C22.1 FMI1.5 L6.2 | length 666.3
  Bottom Layer w6.07: FMI1.5@1409.13,3103.34 ccw(c1409.13,3110.74) FMI1.5@1414.36,3105.51
  Bottom Layer w30: L6.2@947.63,2891.15 947.63,2922.4 cw(c1016.45,2922.4) 967.79,2971.06 cw(c1002.98,2935.87) 1002.98,2985.64 1122.09,2985.64 ccw(c1122.09,3018.82) 1145.55,2995.36 ccw(c1096.16,3044.74) 1166.01,3044.74 C21.1@1166.01,3079.34 cw(c1166.01,2993.24) 1226.89,3054.12 1228.56,3052.45 ccw(c1265.7,3089.6) 1265.7,3037.07 1300.38,3037.07 ccw(c1300.38,3059.19) 1316.02,3043.54 ccw(c1267.4,3092.16) 1336.16,3092.16 C22.1@1336.16,3103.34 FMI1.5@1409.13,3103.34
NetC26_2: C26.2 R25.1 U4.43 | length 709.1
  Top Layer w6: v1(2035.67,1972.27) 2035.42,1972.02 2035.42,1915.4 2038.59,1912.23 U4.43@2038.59,1873.9 ; v2@2289.99,2239.77 cw(c2293.57,2243.36) 2288.5,2243.36 R25.1@2288.5,2263.11 2336.38,2263.11 C26.2@2336.45,2263.18
  Bottom Layer w6: v1(2035.67,1972.27) cw(c2089.35,1918.59) 2089.35,1994.51 2225.62,1994.51 ccw(c2225.62,2044.12) 2260.7,2009.04 ccw(c2189.99,2079.75) 2289.99,2079.75 2289.99,2146.14 2289.99,2149.14 ccw(c2283.69,2149.14) 2283.69,2155.44 2277.96,2155.44 cw(c2277.96,2161.74) 2271.66,2161.74 2271.66,2163.14 cw(c2277.96,2163.14) 2277.96,2169.44 2295.67,2169.44 ccw(c2295.67,2175.74) 2301.97,2175.74 2301.97,2177.14 ccw(c2295.67,2177.14) 2295.67,2183.44 2283.69,2183.44 cw(c2283.69,2189.74) 2277.39,2189.74 2277.39,2191.14 cw(c2283.69,2191.14) 2283.69,2197.44 ccw(c2283.69,2203.74) 2289.99,2203.74 2289.99,2237.77 v2@2289.99,2239.77
  other v2: 2289.99,2242.77
NetC27_1: C27.1 R26.2 U4.41 | length 154.6
  Top Layer w6: U4.41@2070.09,1873.9 2070.09,1918.54 cw(c2086.14,1918.54) 2074.79,1929.9 ccw(c2063.81,1940.88) 2079.34,1940.88 2079.34,1955.55 ccw(c2048.61,1955.55) R26.2@2070.34,1977.28 2116.28,1977.28 C27.1@2116.58,1977.58
NetC40_1: C40.1 U6.1 | length 150
  Top Layer w30: U6.1@777.86,2351.78 814.93,2388.85 cw(c885.64,2318.14) 885.64,2418.14 C40.1@904.72,2418.14
NetC44_2: C44.2 C45.2 L7.2 R54.1 R56.1 | length 1229.4
  Top Layer w30: R56.1@2694.06,2371.24 cw(c2769.63,2371.24) 2716.19,2424.68 2731.04,2439.53 ccw(c2686.55,2484.02) R54.1@2749.47,2484.02 ; R54.1@2749.47,2484.02 cw(c2752.08,2481.41) 2752.08,2485.11 v3(2775.69,2485.11) ccw(c2774.01,2486.78) 2776.38,2486.78 v3(2776.38,2514.01) cw(c2768.95,2514.01) 2774.21,2508.76 R54.1@2749.47,2484.02
  Bottom Layer w30: L7.2@2468.6,2648.83 2490.06,2670.28 cw(c2560.77,2599.57) 2560.77,2699.57 C45.2@2563.17,2699.57 ; C45.2@2563.17,2705.28 C45.2@2563.17,2699.57 ; C44.2@2592.47,2603.15 C44.2@2592.47,2598.15 ; 2631.3,2538.55 ccw(c2690.55,2597.8) 2690.55,2514.01 v3(2776.38,2514.01) ; C45.2@2563.17,2699.57 2563.17,2656.71 ccw(c2663.17,2656.71) 2592.46,2586 C44.2@2592.68,2585.78 ; C44.2@2592.47,2598.15 ccw(c2642.59,2598.15) C44.2@2594.52,2583.93 ; C44.2@2592.47,2598.15 2592.47,2592.35 ccw(c2692.47,2592.35) C44.2@2592.68,2585.78 ; C44.2@2592.68,2585.78 ccw(c2692.47,2592.35) 2621.75,2521.64 2632.34,2511.06 ccw(c2690.94,2569.66) 2690.94,2486.78 2707.94,2486.78 ; C44.2@2592.68,2585.78 C44.2@2594.52,2583.93 ; C44.2@2594.52,2583.93 ccw(c2642.59,2598.15) 2607.15,2562.71 2655.46,2514.39 ccw(c2726.17,2585.11) 2663.88,2506.88 ccw(c2726.17,2585.11) 2691.93,2491.15 ; 2691.93,2491.15 ccw(c2726.17,2585.11) 2707.94,2486.78 ; 2691.93,2491.15 2721.19,2491.15 ccw(c2721.19,2569.2) v3(2776.38,2514.01) ; 2707.94,2486.78 ccw(c2726.17,2585.11) 2726.17,2485.11 v3(2775.69,2485.11) ccw(c2774.01,2486.78) v3@2776.38,2486.78 ; 2707.94,2486.78 v3@2776.38,2486.78 ; v3@2776.38,2486.78 v3(2776.38,2514.01)
NetC60_1: C60.1 U7.K2 | length 41
  Top Layer w6: v5@3401.6,3074.64 3401.86,3074.9 3442.15,3074.9 U7.K2@3442.41,3075.16
  other v5: 3399.6,3074.64
NetC66_1: C66.1 C70.1 F2.1 J5.1 | length 773.4
  Top Layer w30: F2.1@1441.23,402.99 1441.23,471.63 ccw(c1385.59,471.63) C70.1@1424.93,510.97 ccw(c1378.77,557.14) 1444.06,557.14 C66.1@1444.06,608.6 ; v10(1476.8,609.33) cw(c1475.02,611.11) v10@1475.02,608.6 ; C66.1@1444.06,608.6 ccw(c1444.06,613.51) 1447.53,610.04 v3(1476.57,639.08) 1476.57,612.34 cw(c1471.28,612.34) v10@1475.02,608.6 ; C66.1@1444.06,608.6 v10@1475.02,608.6
  Layer 2 w30: v3(1476.57,639.08) v3@1476.8,638.85 ; J5.1@1830.72,547.91 1806.98,547.91 cw(c1806.98,622.07) 1754.54,569.63 1744.13,580.05 ccw(c1673.42,509.33) 1673.42,609.33 1513.11,609.33 ; v3@1476.8,638.85 v10(1476.8,609.33) 1513.11,609.33 ; v3@1476.8,638.85 1501.52,614.13 ccw(c1513.11,625.72) 1513.11,609.33
NetC71_2: C71.2 J5.8 | length 841.8
  Top Layer w8.22: J5.8@1889.78,606.96 1863.29,633.45 cw(c1879.77,649.93) 1856.46,649.93 1856.46,736.91 cw(c1956.46,736.91) 1885.75,807.62 1941.21,863.07 ccw(c1861.15,943.13) 1974.37,943.13 1974.37,1369.15 cw(c2008.98,1369.15) C71.2@1984.51,1393.63
NetC72_2: C72.2 J5.9 | length 841.3
  Top Layer w8.22: J5.9@1811.04,606.96 1835.63,631.55 ccw(c1817.24,649.93) 1843.24,649.93 1843.24,736.91 cw(c1956.46,736.91) 1876.4,816.97 1931.86,872.42 ccw(c1861.15,943.13) 1961.15,943.13 1961.15,1369.15 ccw(c1926.53,1369.15) C72.2@1951.01,1393.63
NetC73_2: C73.2 J1.1 | length 177
  Top Layer w6.07: J1.1@1234.59,1638.12 1275.38,1597.34 ccw(c1286.59,1608.56) 1286.59,1592.69 1357.24,1592.69 ccw(c1357.24,1604.4) 1365.52,1596.12 C73.2@1384.59,1615.2
NetC74_2: C74.2 J1.2 | length 175.9
  Top Layer w6.07: J1.2@1234.59,1538.12 1272.09,1575.62 cw(c1286.59,1561.11) 1286.59,1581.63 1357.14,1581.63 cw(c1357.14,1569.66) 1365.59,1578.12 C74.2@1384.59,1559.12
NetD1_1: D1.1 R2.1 | length 326.4
  Top Layer w10: D1.1@140.35,369.48 140.35,314.57 ccw(c160.01,314.57) 146.1,300.67 ccw(c177.52,332.08) 177.52,287.65 296.76,287.65 ccw(c296.76,327.64) 325.04,299.37 ccw(c289.05,335.35) 335.44,314.41 ccw(c289.05,335.35) 338.7,324.17 ccw(c289.05,335.35) 339.95,335.35 R2.1@339.95,365.91
NetD3_1: D3.1 R81.1 | length 135.5
  Top Layer w10: R81.1@2556.38,946.26 ccw(c2554.85,947.79) 2557.01,947.79 D3.1@2557.01,1081.6
NetD4_1: D4.1 R82.1 | length 135.5
  Top Layer w10: R82.1@2666.38,946.08 D4.1@2666.38,1081.6
NetD5_1: D5.1 R83.1 | length 137.8
  Top Layer w10: D5.1@2775.75,1081.6 2775.75,964.34 ccw(c2801.94,964.34) R83.1@2783.42,945.83
NetF1_1: F1.1 S3.2 | length 406.5
  Top Layer w30: S3.2@110.18,924.32 83.82,924.32 cw(c83.82,959.41) 59.02,934.6 cw(c104.46,980.04) 40.19,980.04 40.19,1160.52 cw(c107.25,1160.52) 59.83,1207.94 63.92,1212.02 cw(c120.84,1155.1) F1.1@120.84,1235.6
NetFMI1_4: FMI1.4 R19.2 | length 167.8
  Top Layer w20: FMI1.4@1414.36,3005.51 ccw(c1417.4,3008.56) 1417.4,3004.25 R19.2@1581.84,3004.25
NetJ4_2: J4.2 P6.1 | length 243.2
  Layer 2 w30: J4.2@3613.66,1025.68 3613.66,1029.89 cw(c3713.66,1029.89) 3642.95,1100.6 3687.97,1145.62 ccw(c3628.35,1205.24) 3712.66,1205.24 P6.1@3712.66,1235.79
NetL1_1: L1.1 U1.3 | length 157.4
  Top Layer w30: U1.3@410.67,742.39 L1.1@563.13,742.39 ; L1.1@560.13,742.39 ccw(c560.13,748.7) L1.1@564.59,744.24
NetL3_1: L3.1 U3(NC).3 | length 140.2
  Top Layer w30: 939.72,743.31 L3.1@1078.61,743.31 ; L3.1@1074.61,743.31 L3.1@1075.53,744.24
NetL5_1: L5.1 L6.1 R8.2 R11.2 R12.2 R13.2 | length 1387.7
  Bottom Layer w30: R12.2@855.52,2735.3 855.52,2818.92 ccw(c852.48,2818.92) L5.1@854.63,2821.07 ; R13.2@949.8,2735.3 949.8,2815.84 ccw(c942.4,2815.84) L6.1@947.63,2821.07 L5.1@854.63,2821.07 ; R8.2@1278.35,3402.57 R11.2@1278.35,3335.66 873.42,3335.66 ccw(c873.42,3235.66) 802.71,3306.37 784.29,3287.94 ccw(c855,3217.23) 755,3217.23 755,2888.99 ccw(c825.19,2888.99) 775.56,2839.36 ccw(c819.7,2883.51) 819.7,2821.07 L5.1@854.63,2821.07
NetP6_17: P6.17 R88.2 | length 99
  Bottom Layer w20: P6.17@3712.66,2035.79 3791.59,2035.79 cw(c3791.59,2010.27) R88.2@3809.64,2028.31
NetR15_1: R15.1 tp1.1 | length 209.7
  Top Layer w6: tp1.1@1793.44,3060.12 1883.99,2969.58 cw(c1813.28,2898.87) 1913.28,2898.87 R15.1@1913.28,2895.75
NetR16_1: R16.1 tp2.1 | length 189.9
  Top Layer w6: tp2.1@1905.1,3060.12 1947.85,3017.37 cw(c1877.14,2946.66) 1977.14,2946.66 R16.1@1977.14,2895.75
NetR27_2: R27.2 S2.2 | length 97.6
  Top Layer w6: S2.2@3544.26,344.38 3544.26,300.4 ccw(c3612.59,300.4) R27.2@3564.27,252.09
NetR51_1: R51.1 U4.19 | length 485.4
  Top Layer w6: U4.19@2196.78,1606.89 2217.62,1606.89 ; v2@2395.27,1471.5 2289.17,1577.6 ccw(c2218.46,1506.89) 2218.46,1606.89 2217.62,1606.89 ; v2@2399.07,1466.86 2288.33,1577.6 ccw(c2217.62,1506.89) 2217.62,1606.89
  other v2: 2400.13,1465.86
NetR55_1: R55.1 U6.10 | length 259.1
  Top Layer w30: U6.10@677.86,1901.78 701.6,1878.05 ccw(c772.31,1948.76) 772.31,1848.76 R55.1@919.3,1848.76
NetR74_2: R74.2 U7.U5 | length 130.8
  Top Layer w6: U7.U5@3501.47,2937.37 ccw(c3501.47,2960.56) 3517.87,2944.16 v4(3528.76,2955.05)
  Bottom Layer w6: R74.2@3432.34,2952.28 cw(c3439.03,2945.59) 3439.03,2955.05 v4(3528.76,2955.05)
NetR75_2: R75.2 R77.1 U7.W5 | length 552.1
  Top Layer w6: U7.W5@3501.47,2898 cw(c3521.54,2898) 3507.34,2912.19 v4(3515.78,2920.63)
  Bottom Layer w6: v2@3022.2,2866.57 3461.72,2866.57 ccw(c3461.72,2920.63) v4(3515.78,2920.63)
  other v2: 3018.2,2866.57
NetR76_5: R76.5 U7.J2 | length 3175.9
  Top Layer w6: R76.5@2489.51,1642.03 3065.22,1642.03 ccw(c3065.22,1727.02) 3150.21,1727.02 3150.21,1747.09 3150.21,1750.09 ccw(c3143.01,1750.09) 3143.01,1757.29 3142.41,1757.29 cw(c3142.41,1764.49) 3135.21,1764.49 3135.21,1766.09 cw(c3142.41,1766.09) 3142.41,1773.29 3158.01,1773.29 ccw(c3158.01,1780.49) 3165.21,1780.49 3165.21,1782.09 ccw(c3158.01,1782.09) 3158.01,1789.29 3142.41,1789.29 cw(c3142.41,1796.49) 3135.21,1796.49 3135.21,1798.09 cw(c3142.41,1798.09) 3142.41,1805.29 3158.01,1805.29 ccw(c3158.01,1812.49) 3165.21,1812.49 3165.21,1814.09 ccw(c3158.01,1814.09) 3158.01,1821.29 3142.41,1821.29 cw(c3142.41,1828.49) 3135.21,1828.49 3135.21,1830.09 cw(c3142.41,1830.09) 3142.41,1837.29 3158.01,1837.29 ccw(c3158.01,1844.49) 3165.21,1844.49 3165.21,1846.09 ccw(c3158.01,1846.09) 3158.01,1853.29 3142.41,1853.29 cw(c3142.41,1860.49) 3135.21,1860.49 3135.21,1862.09 cw(c3142.41,1862.09) 3142.41,1869.29 3158.01,1869.29 ccw(c3158.01,1876.49) 3165.21,1876.49 3165.21,1878.09 ccw(c3158.01,1878.09) 3158.01,1885.29 3142.41,1885.29 cw(c3142.41,1892.49) 3135.21,1892.49 3135.21,1894.09 cw(c3142.41,1894.09) 3142.41,1901.29 3158.01,1901.29 ccw(c3158.01,1908.49) 3165.21,1908.49 3165.21,1910.09 ccw(c3158.01,1910.09) 3158.01,1917.29 3142.41,1917.29 cw(c3142.41,1924.49) 3135.21,1924.49 3135.21,1926.09 cw(c3142.41,1926.09) 3142.41,1933.29 3158.01,1933.29 ccw(c3158.01,1940.49) 3165.21,1940.49 3165.21,1942.09 ccw(c3158.01,1942.09) 3158.01,1949.29 3142.41,1949.29 cw(c3142.41,1956.49) 3135.21,1956.49 3135.21,1958.09 cw(c3142.41,1958.09) 3142.41,1965.29 3158.01,1965.29 ccw(c3158.01,1972.49) 3165.21,1972.49 3165.21,1974.09 ccw(c3158.01,1974.09) 3158.01,1981.29 3142.41,1981.29 cw(c3142.41,1988.49) 3135.21,1988.49 3135.21,1990.09 cw(c3142.41,1990.09) 3142.41,1997.29 3158.01,1997.29 ccw(c3158.01,2004.49) 3165.21,2004.49 3165.21,2006.09 ccw(c3158.01,2006.09) 3158.01,2013.29 3142.41,2013.29 cw(c3142.41,2020.49) 3135.21,2020.49 3135.21,2022.09 cw(c3142.41,2022.09) 3142.41,2029.29 3158.01,2029.29 ccw(c3158.01,2036.49) 3165.21,2036.49 3165.21,2038.09 ccw(c3158.01,2038.09) 3158.01,2045.29 3142.41,2045.29 cw(c3142.41,2052.49) 3135.21,2052.49 3135.21,2054.09 cw(c3142.41,2054.09) 3142.41,2061.29 3158.01,2061.29 ccw(c3158.01,2068.49) 3165.21,2068.49 3165.21,2070.09 ccw(c3158.01,2070.09) 3158.01,2077.29 3142.41,2077.29 cw(c3142.41,2084.49) 3135.21,2084.49 3135.21,2086.09 cw(c3142.41,2086.09) 3142.41,2093.29 3158.01,2093.29 ccw(c3158.01,2100.49) 3165.21,2100.49 3165.21,2102.09 ccw(c3158.01,2102.09) 3158.01,2109.29 3142.41,2109.29 cw(c3142.41,2116.49) 3135.21,2116.49 3135.21,2118.09 cw(c3142.41,2118.09) 3142.41,2125.29 3158.01,2125.29 ccw(c3158.01,2132.49) 3165.21,2132.49 3165.21,2134.09 ccw(c3158.01,2134.09) 3158.01,2141.29 3142.41,2141.29 cw(c3142.41,2148.49) 3135.21,2148.49 3135.21,2150.09 cw(c3142.41,2150.09) 3142.41,2157.29 3158.01,2157.29 ccw(c3158.01,2164.49) 3165.21,2164.49 3165.21,2166.09 ccw(c3158.01,2166.09) 3158.01,2173.29 3142.41,2173.29 cw(c3142.41,2180.49) 3135.21,2180.49 3135.21,2182.09 cw(c3142.41,2182.09) 3142.41,2189.29 3158.01,2189.29 ccw(c3158.01,2196.49) 3165.21,2196.49 3165.21,2198.09 ccw(c3158.01,2198.09) 3158.01,2205.29 3142.41,2205.29 cw(c3142.41,2212.49) 3135.21,2212.49 3135.21,2214.09 cw(c3142.41,2214.09) 3142.41,2221.29 3158.01,2221.29 ccw(c3158.01,2228.49) 3165.21,2228.49 3165.21,2230.09 ccw(c3158.01,2230.09) 3158.01,2237.29 3142.41,2237.29 cw(c3142.41,2244.49) 3135.21,2244.49 3135.21,2246.09 cw(c3142.41,2246.09) 3142.41,2253.29 3158.01,2253.29 ccw(c3158.01,2260.49) 3165.21,2260.49 3165.21,2262.09 ccw(c3158.01,2262.09) 3158.01,2269.29 3142.41,2269.29 cw(c3142.41,2276.49) 3135.21,2276.49 3135.21,2278.09 cw(c3142.41,2278.09) 3142.41,2285.29 3158.01,2285.29 ccw(c3158.01,2292.49) 3165.21,2292.49 3165.21,2294.09 ccw(c3158.01,2294.09) 3158.01,2301.29 3144.2,2301.29 cw(c3144.2,2308.49) 3137,2308.49 3137,2310.09 cw(c3144.2,2310.09) 3144.2,2317.29 3157.41,2317.29 ccw(c3157.41,2324.49) 3164.61,2324.49 3164.61,2326.09 ccw(c3157.41,2326.09) 3157.41,2333.29 cw(c3157.41,2340.49) 3150.21,2340.49 3150.21,2389.14 3150.21,2966.71 cw(c3250.21,2966.71) 3179.5,3037.42 v2(3214.15,3072.07) ; v2(3402.65,3119.85) 3411.57,3119.85 cw(c3411.57,3098.52) 3426.65,3113.61 U7.J2@3443.12,3097.13
  Bottom Layer w6: v2(3214.15,3072.07) 3232.65,3090.56 cw(c3303.36,3019.85) 3303.36,3119.85 v2(3402.65,3119.85)
NetR76_6: R76.6 U7.H5 | length 3196.5
  Top Layer w6: R76.6@2489.51,1676.68 3020.07,1676.68 ccw(c3020.07,1776.68) 3120.07,1776.68 3120.07,2691.35 3120.07,2694.35 ccw(c3113.77,2694.35) 3113.77,2700.65 3110.37,2700.65 cw(c3110.37,2706.95) 3104.07,2706.95 3104.07,2708.35 cw(c3110.37,2708.35) 3110.37,2714.65 3129.77,2714.65 ccw(c3129.77,2720.95) 3136.07,2720.95 3136.07,2722.35 ccw(c3129.77,2722.35) 3129.77,2728.65 3110.37,2728.65 cw(c3110.37,2734.95) 3104.07,2734.95 3104.07,2736.35 cw(c3110.37,2736.35) 3110.37,2742.65 3129.77,2742.65 ccw(c3129.77,2748.95) 3136.07,2748.95 3136.07,2750.35 ccw(c3129.77,2750.35) 3129.77,2756.65 3110.37,2756.65 cw(c3110.37,2762.95) 3104.07,2762.95 3104.07,2764.35 cw(c3110.37,2764.35) 3110.37,2770.65 3129.77,2770.65 ccw(c3129.77,2776.95) 3136.07,2776.95 3136.07,2778.35 ccw(c3129.77,2778.35) 3129.77,2784.65 3110.37,2784.65 cw(c3110.37,2790.95) 3104.07,2790.95 3104.07,2792.35 cw(c3110.37,2792.35) 3110.37,2798.65 3129.77,2798.65 ccw(c3129.77,2804.95) 3136.07,2804.95 3136.07,2806.35 ccw(c3129.77,2806.35) 3129.77,2812.65 3110.37,2812.65 cw(c3110.37,2818.95) 3104.07,2818.95 3104.07,2820.35 cw(c3110.37,2820.35) 3110.37,2826.65 3129.77,2826.65 ccw(c3129.77,2832.95) 3136.07,2832.95 3136.07,2834.35 ccw(c3129.77,2834.35) 3129.77,2840.65 3110.37,2840.65 cw(c3110.37,2846.95) 3104.07,2846.95 3104.07,2848.35 cw(c3110.37,2848.35) 3110.37,2854.65 3129.77,2854.65 ccw(c3129.77,2860.95) 3136.07,2860.95 3136.07,2862.35 ccw(c3129.77,2862.35) 3129.77,2868.65 3110.37,2868.65 cw(c3110.37,2874.95) 3104.07,2874.95 3104.07,2876.35 cw(c3110.37,2876.35) 3110.37,2882.65 3129.77,2882.65 ccw(c3129.77,2888.95) 3136.07,2888.95 3136.07,2890.35 ccw(c3129.77,2890.35) 3129.77,2896.65 3110.37,2896.65 cw(c3110.37,2902.95) 3104.07,2902.95 3104.07,2904.35 cw(c3110.37,2904.35) 3110.37,2910.65 3129.77,2910.65 ccw(c3129.77,2916.95) 3136.07,2916.95 3136.07,2918.35 ccw(c3129.77,2918.35) 3129.77,2924.65 3110.37,2924.65 cw(c3110.37,2930.95) 3104.07,2930.95 3104.07,2932.35 cw(c3110.37,2932.35) 3110.37,2938.65 3129.77,2938.65 ccw(c3129.77,2944.95) 3136.07,2944.95 3136.07,2946.35 ccw(c3129.77,2946.35) 3129.77,2952.65 3110.37,2952.65 cw(c3110.37,2958.95) 3104.07,2958.95 3104.07,2960.35 cw(c3110.37,2960.35) 3110.37,2966.65 3129.77,2966.65 ccw(c3129.77,2972.95) 3136.07,2972.95 3136.07,2974.35 ccw(c3129.77,2974.35) 3129.77,2980.65 3110.37,2980.65 cw(c3110.37,2986.95) 3104.07,2986.95 3104.07,2988.35 cw(c3110.37,2988.35) 3110.37,2994.65 3127.06,2994.65 ccw(c3127.06,3000.95) 3133.36,3000.95 3133.36,3002.35 ccw(c3127.06,3002.35) 3127.06,3008.65 3113.77,3008.65 cw(c3113.77,3014.95) 3107.47,3014.95 3107.47,3016.35 cw(c3113.77,3016.35) 3113.77,3022.65 ccw(c3113.77,3028.95) 3120.07,3028.95 3120.07,3089.07 3120.07,3209.23 v2(3119.72,3209.58) ; U7.H5@3501.47,3114.53 v2@3501.47,3204.25
  Bottom Layer w6: v2(3119.72,3209.58) cw(c3175.24,3154.05) 3175.24,3232.58 3458.56,3232.58 cw(c3458.56,3172.56) v2(3501,3215)
NetR76_7: R76.7 U7.H4 | length 3218.7
  Top Layer w6: R76.7@2489.51,1708.18 2984.47,1708.18 ccw(c2984.47,1812.31) 3088.61,1812.31 3088.61,1842.77 3088.61,1845.77 ccw(c3081.11,1845.77) 3081.11,1853.27 3076.68,1853.27 cw(c3076.68,1860.77) 3076.68,1868.27 3092.05,1868.27 ccw(c3092.05,1875.77) 3092.05,1883.27 3076.68,1883.27 cw(c3076.68,1890.77) 3076.68,1898.27 3092.05,1898.27 ccw(c3092.05,1905.77) 3092.05,1913.27 3076.68,1913.27 cw(c3076.68,1920.77) 3076.68,1928.27 3092.05,1928.27 ccw(c3092.05,1935.77) 3092.05,1943.27 3076.68,1943.27 cw(c3076.68,1950.77) 3076.68,1958.27 3092.05,1958.27 ccw(c3092.05,1965.77) 3092.05,1973.27 3076.68,1973.27 cw(c3076.68,1980.77) 3076.68,1988.27 3092.05,1988.27 ccw(c3092.05,1995.77) 3092.05,2003.27 3076.68,2003.27 cw(c3076.68,2010.77) 3076.68,2018.27 3092.05,2018.27 ccw(c3092.05,2025.77) 3092.05,2033.27 3076.68,2033.27 cw(c3076.68,2040.77) 3076.68,2048.27 3092.05,2048.27 ccw(c3092.05,2055.77) 3092.05,2063.27 3076.68,2063.27 cw(c3076.68,2070.77) 3076.68,2078.27 3092.05,2078.27 ccw(c3092.05,2085.77) 3092.05,2093.27 3076.68,2093.27 cw(c3076.68,2100.77) 3076.68,2108.27 3092.05,2108.27 ccw(c3092.05,2115.77) 3092.05,2123.27 3076.68,2123.27 cw(c3076.68,2130.77) 3076.68,2138.27 3092.05,2138.27 ccw(c3092.05,2145.77) 3092.05,2153.27 3076.68,2153.27 cw(c3076.68,2160.77) 3076.68,2168.27 3092.05,2168.27 ccw(c3092.05,2175.77) 3092.05,2183.27 3076.68,2183.27 cw(c3076.68,2190.77) 3076.68,2198.27 3092.05,2198.27 ccw(c3092.05,2205.77) 3092.05,2213.27 3076.68,2213.27 cw(c3076.68,2220.77) 3076.68,2228.27 3092.05,2228.27 ccw(c3092.05,2235.77) 3092.05,2243.27 3076.68,2243.27 cw(c3076.68,2250.77) 3076.68,2258.27 3092.05,2258.27 ccw(c3092.05,2265.77) 3092.05,2273.27 3076.68,2273.27 cw(c3076.68,2280.77) 3076.68,2288.27 3092.05,2288.27 ccw(c3092.05,2295.77) 3092.05,2303.27 3076.68,2303.27 cw(c3076.68,2310.77) 3076.68,2318.27 3081.11,2318.27 ccw(c3081.11,2325.77) 3088.61,2325.77 3088.61,2412.44 v2@3088.61,3138.04 ; v2(3467.61,3192.5) 3461.18,3186.07 3461.18,3185.77 cw(c3461.18,3165.16) 3481.78,3165.16 U7.H4@3481.78,3114.53
  Bottom Layer w6: v2(3087.85,3138.04) 3113.01,3163.21 cw(c3183.72,3092.5) 3183.72,3192.5 v2(3467.61,3192.5)
NetR76_8: R76.8 U7.H3 | length 3208.8
  Top Layer w6: R76.8@2489.51,1742.82 2957.83,1742.82 ccw(c2957.83,1842.82) 3057.83,1842.82 3057.83,1902.82 3057.83,2420.6 3057.83,2423.6 ccw(c3050.33,2423.6) 3050.33,2431.1 3047.38,2431.1 cw(c3047.38,2438.6) 3047.38,2446.1 3062.38,2446.1 ccw(c3062.38,2453.6) 3062.38,2461.1 3047.38,2461.1 cw(c3047.38,2468.6) 3047.38,2476.1 3062.38,2476.1 ccw(c3062.38,2483.6) 3062.38,2491.1 3047.38,2491.1 cw(c3047.38,2498.6) 3047.38,2506.1 3062.38,2506.1 ccw(c3062.38,2513.6) 3062.38,2521.1 3047.38,2521.1 cw(c3047.38,2528.6) 3047.38,2536.1 3062.38,2536.1 ccw(c3062.38,2543.6) 3062.38,2551.1 3047.38,2551.1 cw(c3047.38,2558.6) 3047.38,2566.1 3062.38,2566.1 ccw(c3062.38,2573.6) 3062.38,2581.1 3047.38,2581.1 cw(c3047.38,2588.6) 3047.38,2596.1 3062.38,2596.1 ccw(c3062.38,2603.6) 3062.38,2611.1 3047.38,2611.1 cw(c3047.38,2618.6) 3047.38,2626.1 3062.38,2626.1 ccw(c3062.38,2633.6) 3062.38,2641.1 3047.38,2641.1 cw(c3047.38,2648.6) 3047.38,2656.1 3062.38,2656.1 ccw(c3062.38,2663.6) 3062.38,2671.1 3047.38,2671.1 cw(c3047.38,2678.6) 3047.38,2686.1 3062.38,2686.1 ccw(c3062.38,2693.6) 3062.38,2701.1 3047.38,2701.1 cw(c3047.38,2708.6) 3047.38,2716.1 3062.38,2716.1 ccw(c3062.38,2723.6) 3062.38,2731.1 3047.38,2731.1 cw(c3047.38,2738.6) 3047.38,2746.1 3062.38,2746.1 ccw(c3062.38,2753.6) 3062.38,2761.1 3047.38,2761.1 cw(c3047.38,2768.6) 3047.38,2776.1 3062.38,2776.1 ccw(c3062.38,2783.6) 3062.38,2791.1 3047.38,2791.1 cw(c3047.38,2798.6) 3047.38,2806.1 3062.38,2806.1 ccw(c3062.38,2813.6) 3062.38,2821.1 3047.38,2821.1 cw(c3047.38,2828.6) 3047.38,2836.1 3062.38,2836.1 ccw(c3062.38,2843.6) 3062.38,2851.1 3047.38,2851.1 cw(c3047.38,2858.6) 3047.38,2866.1 3062.38,2866.1 ccw(c3062.38,2873.6) 3062.38,2881.1 3047.38,2881.1 cw(c3047.38,2888.6) 3047.38,2896.1 3062.38,2896.1 ccw(c3062.38,2903.6) 3062.38,2911.1 3047.38,2911.1 cw(c3047.38,2918.6) 3047.38,2926.1 3062.38,2926.1 ccw(c3062.38,2933.6) 3062.38,2941.1 3047.38,2941.1 cw(c3047.38,2948.6) 3047.38,2956.1 3061.44,2956.1 ccw(c3061.44,2963.6) 3061.44,2971.1 3057.82,2971.1 cw(c3057.82,2978.6) 3057.82,2986.1 ccw(c3057.83,2993.6) 3057.83,3001.1 3050.32,3001.1 cw(c3050.32,3008.6) 3050.32,3016.1 ccw(c3050.33,3023.6) 3057.83,3023.6 3057.83,3052.47 v2(3057.81,3053.18) ; v2(3451.93,3156.62) cw(c3427.4,3132.09) 3462.1,3132.09 U7.H3@3462.1,3114.53
  Bottom Layer w6: v2(3057.81,3053.18) 3153.93,3149.29 cw(c3224.64,3078.58) 3224.64,3178.58 3398.9,3178.58 cw(c3398.9,3103.59) v2(3451.93,3156.62)
NetR78_1: R78.1 U7.W6 | length 758.1
  Top Layer w6: U7.W6@3521.15,2898 cw(c3526.16,2898) 3522.61,2901.53 3539.73,2918.65 ccw(c3535.79,2922.59) v4(3541.36,2922.59)
  Bottom Layer w6: v2(2887.02,2763.02) 3240.58,2763.02 ccw(c3240.58,2815.24) 3277.51,2778.31 3317.41,2818.21 cw(c3388.12,2747.5) 3388.12,2847.5 3466.27,2847.5 ccw(c3466.27,2922.59) v4(3541.36,2922.59)
NetR80_5: R80.5 U7.J6 | length 3143
  Top Layer w6: R80.5@2489.51,1499.31 3175.21,1499.31 ccw(c3175.21,1599.31) 3275.21,1599.31 3275.21,3322.07 cw(c3319.52,3322.07) v2(3319.52,3366.38) ; U7.J6@3521.15,3094.85 3521.15,3096.42 3526.93,3102.2 3526.93,3136.68 cw(c3546.18,3136.68) 3532.57,3150.29 3562.31,3180.04 ccw(c3523.09,3219.26) v2(3578.56,3219.26)
  Bottom Layer w6: v2(3319.52,3366.38) ccw(c3320.45,3366.38) 3320.45,3365.45 3478.56,3365.45 cw(c3478.56,3265.45) 3578.56,3265.45 v2(3578.56,3219.26)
